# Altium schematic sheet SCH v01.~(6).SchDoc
size A3; SheetNumber: 1; SheetTotal: 1
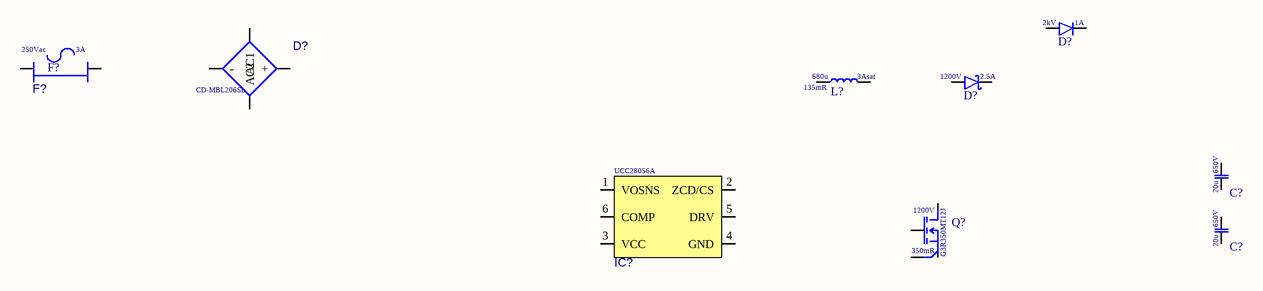
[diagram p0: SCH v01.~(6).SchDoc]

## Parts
(Parts that share a designator on the sheet are numbered #1, #2 ... from top to bottom, then left to right.)
C?#1  Voltage Rating: 650V  Capacitance: 20u  [C4AQCBW5200A3FJ]  (hidden comment: Generic Capacitor model)
C?#2  Voltage Rating: 650V  Capacitance: 20u  [C4AQCBW5200A3FJ]  (hidden comment: Generic Capacitor model)
D?#1  Forward Current: 1A  Reverse Voltage: 2kV  [SOD-123FL]  (hidden comment: Diode)
D?#2  CD-MBL206SL  [CD-MBL206SL]
D?#3  Forward Current: 2.5A  Reverse Voltage: 1200V  [DO-214-2]  (hidden comment: Diode Schottky)
F?#1  Voltage: 250Vac  Hold Current: 3A  (hidden comment: Fuse no FP)  (graphical)
F?#2  64600001003  [64600001003]  (value not drawn)
IC?  UCC28056A  [SOT-23-6]
L?  Resistance: 135mR  Saturation current: 3Asat  Inductance: 680u  [60B684C]  (hidden comment: Inductor)
Q?  Manufacturer Part Number: G3R350MT12J  Rds: 350mR  Voltage: 1200V  [TO-263-7 D2PAK]  (hidden comment: Nmos_KS)

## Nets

Not connected (* = marked no-connect by the designer): C?#1 1 2; C?#2 1 2; D?#1 A K; D?#2 + - AC1 AC2; D?#3 A K; F?#2 1 2; IC? 1(VOSNS) 2(ZCD/CS) 3(VCC) 4(GND) 5(DRV) 6(COMP); L? 1 2; Q? D G KS S

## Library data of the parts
C?#1 C?#2 = Cap: Manufacturer: Kemet
D?#1 = Diode: General Diode symbol; Manufacturer: MCC; Manufacturer Part Number: GS1Z-LTP
D?#2 = CD-MBL206SL: Diode Bridge 600V 2A; Manufacturer: Bourns
D?#3 = Diode Schottky: General Schottky Diode symbol; Manufacturer: GenerSiC; Manufacturer Part Number: GB01SLT12-214
F?#1 = Fuse no FP: Generic fuse symbol - no FP; Manufacturer: Littlefuse; Manufacturer Part Number: 06173.15MXP
F?#2 = 64600001003: Fuse Holder 5X20MM 250V 6.3A; Manufacturer: Littlefuse
IC? = UCC28056A: PFC TM IC; Manufacturer: Texas Instruments
L? = Inductor: Generic Inductor symbol; Manufacturer: Murata
Q? = Nmos_KS: Generic Nmos symbol with Kelvin Source; Manufacturer: GeneSiC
